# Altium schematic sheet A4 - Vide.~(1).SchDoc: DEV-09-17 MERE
size A4; Date: 22/11/2017; Organization: Altium Limited; Address1: L3, 12a Rodborough Rd; Address2: Frenchs Forest; Address3: NSW; Address4: Australia 2086; Revision: 1.0; SheetNumber: 2; SheetTotal: 4; PageSetup: Record=PageOptions¦CenterHorizontal=True¦CenterVertical=True¦PrintScale=0.97¦XCorrection=1.00¦YCorrection=1.00¦PrintKind=0¦BorderSize=5000000¦LeftOffset=0¦BottomOffset=0¦Orientation=2¦PaperLength=1000¦PaperWidth=1000¦Scale=100¦PaperSource=7¦PrintQuality=-3¦MediaType=1¦DitherType=10¦PaperKind=A4¦PrintScaleMode=1
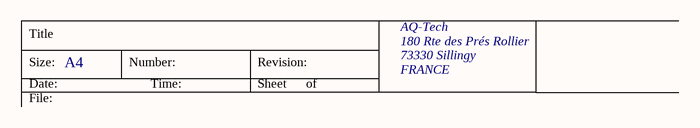
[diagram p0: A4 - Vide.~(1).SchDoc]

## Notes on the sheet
- Title
- Size:
- Date:
- A4
- Number:
- Time:
- Revision:
- Sheet
- of
- AQ-Tech
- 180 Rte des Prés Rollier
- 73330 Sillingy
- FRANCE
- File:
